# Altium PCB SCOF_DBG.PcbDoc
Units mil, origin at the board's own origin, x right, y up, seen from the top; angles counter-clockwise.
Board outline 1365.03 x 1565.05 mil, 2 copper layers (Top Layer, Bottom Layer); 21 components, 22 nets, 103 pads, 92 vias.
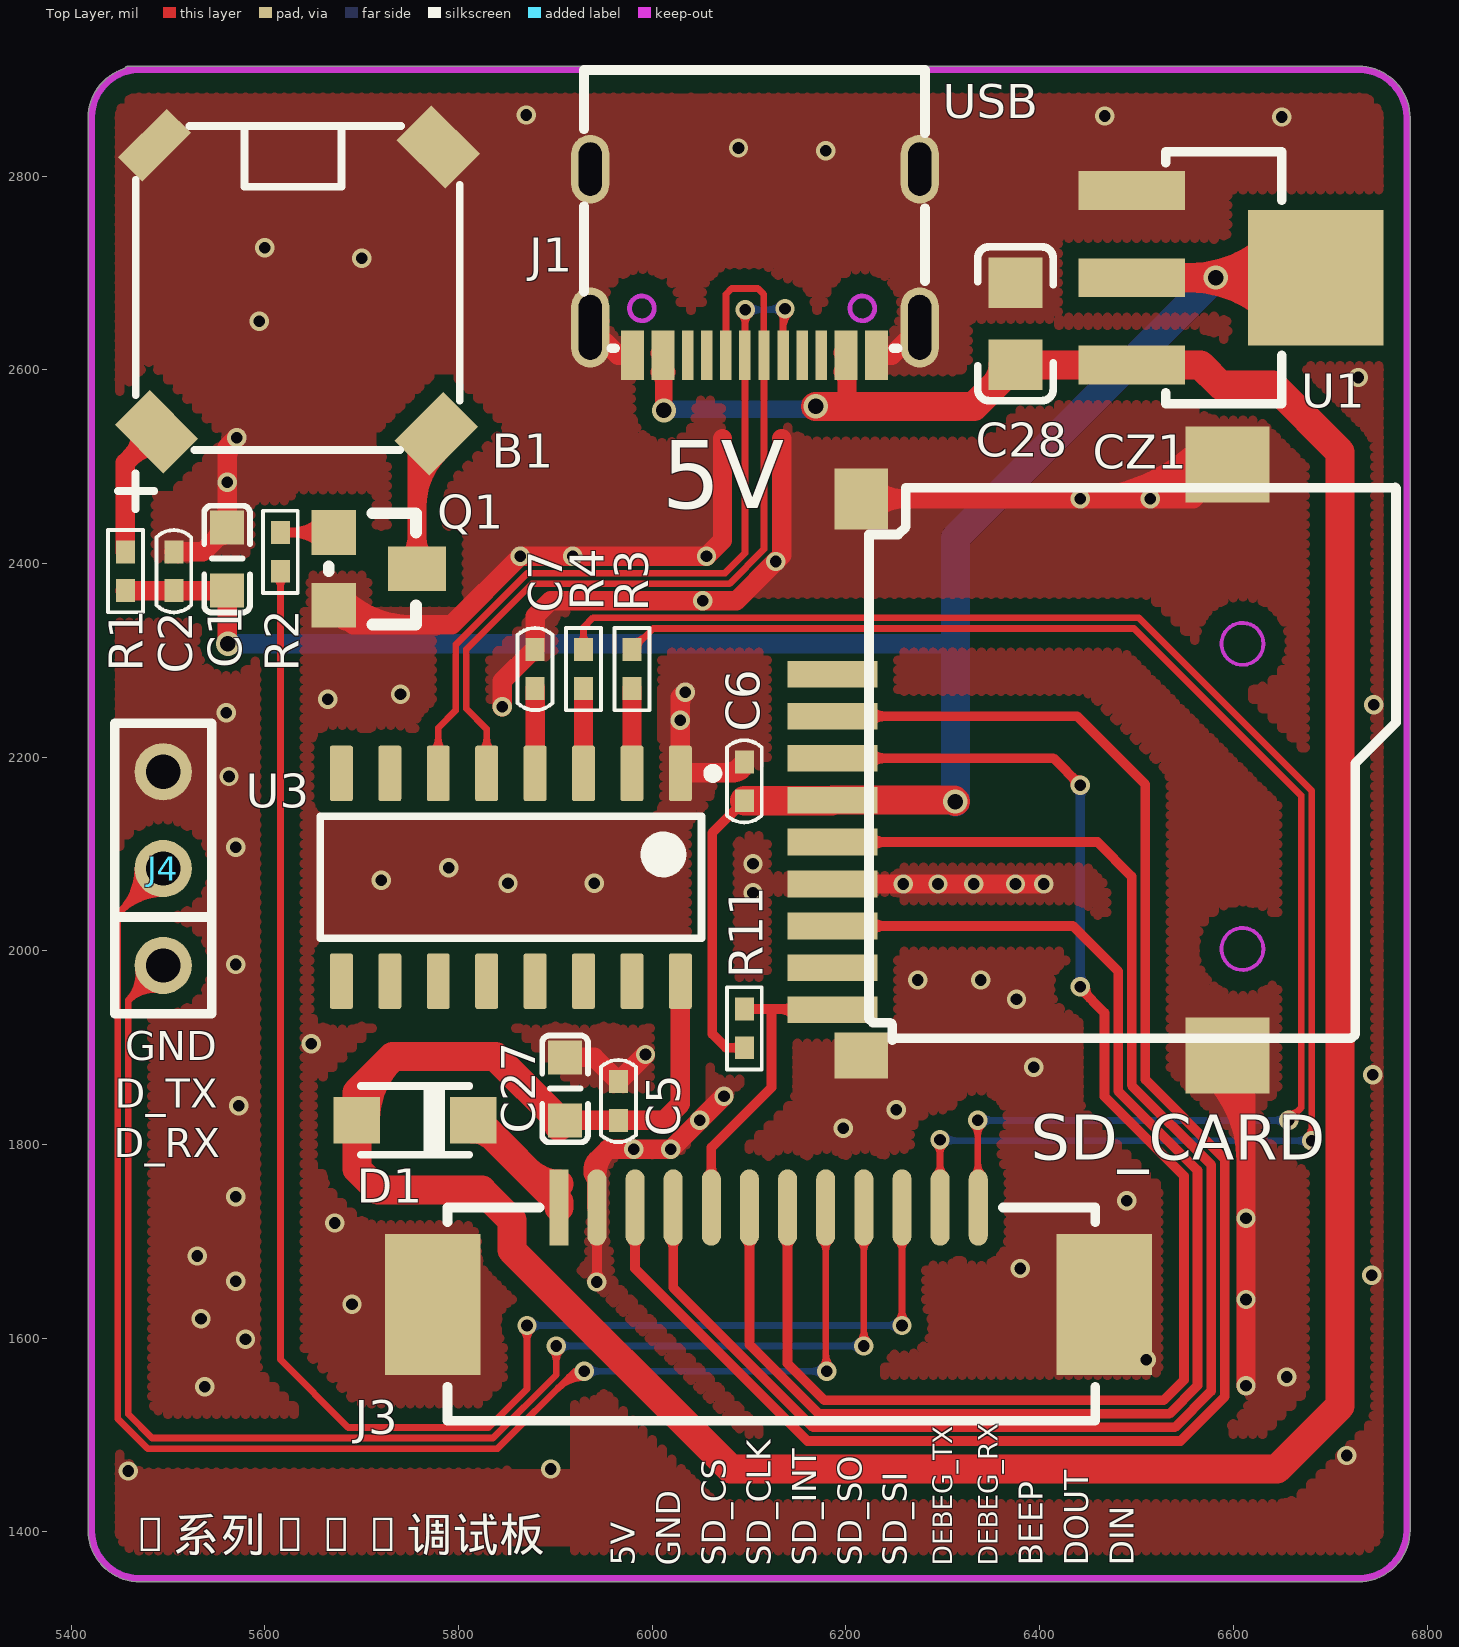
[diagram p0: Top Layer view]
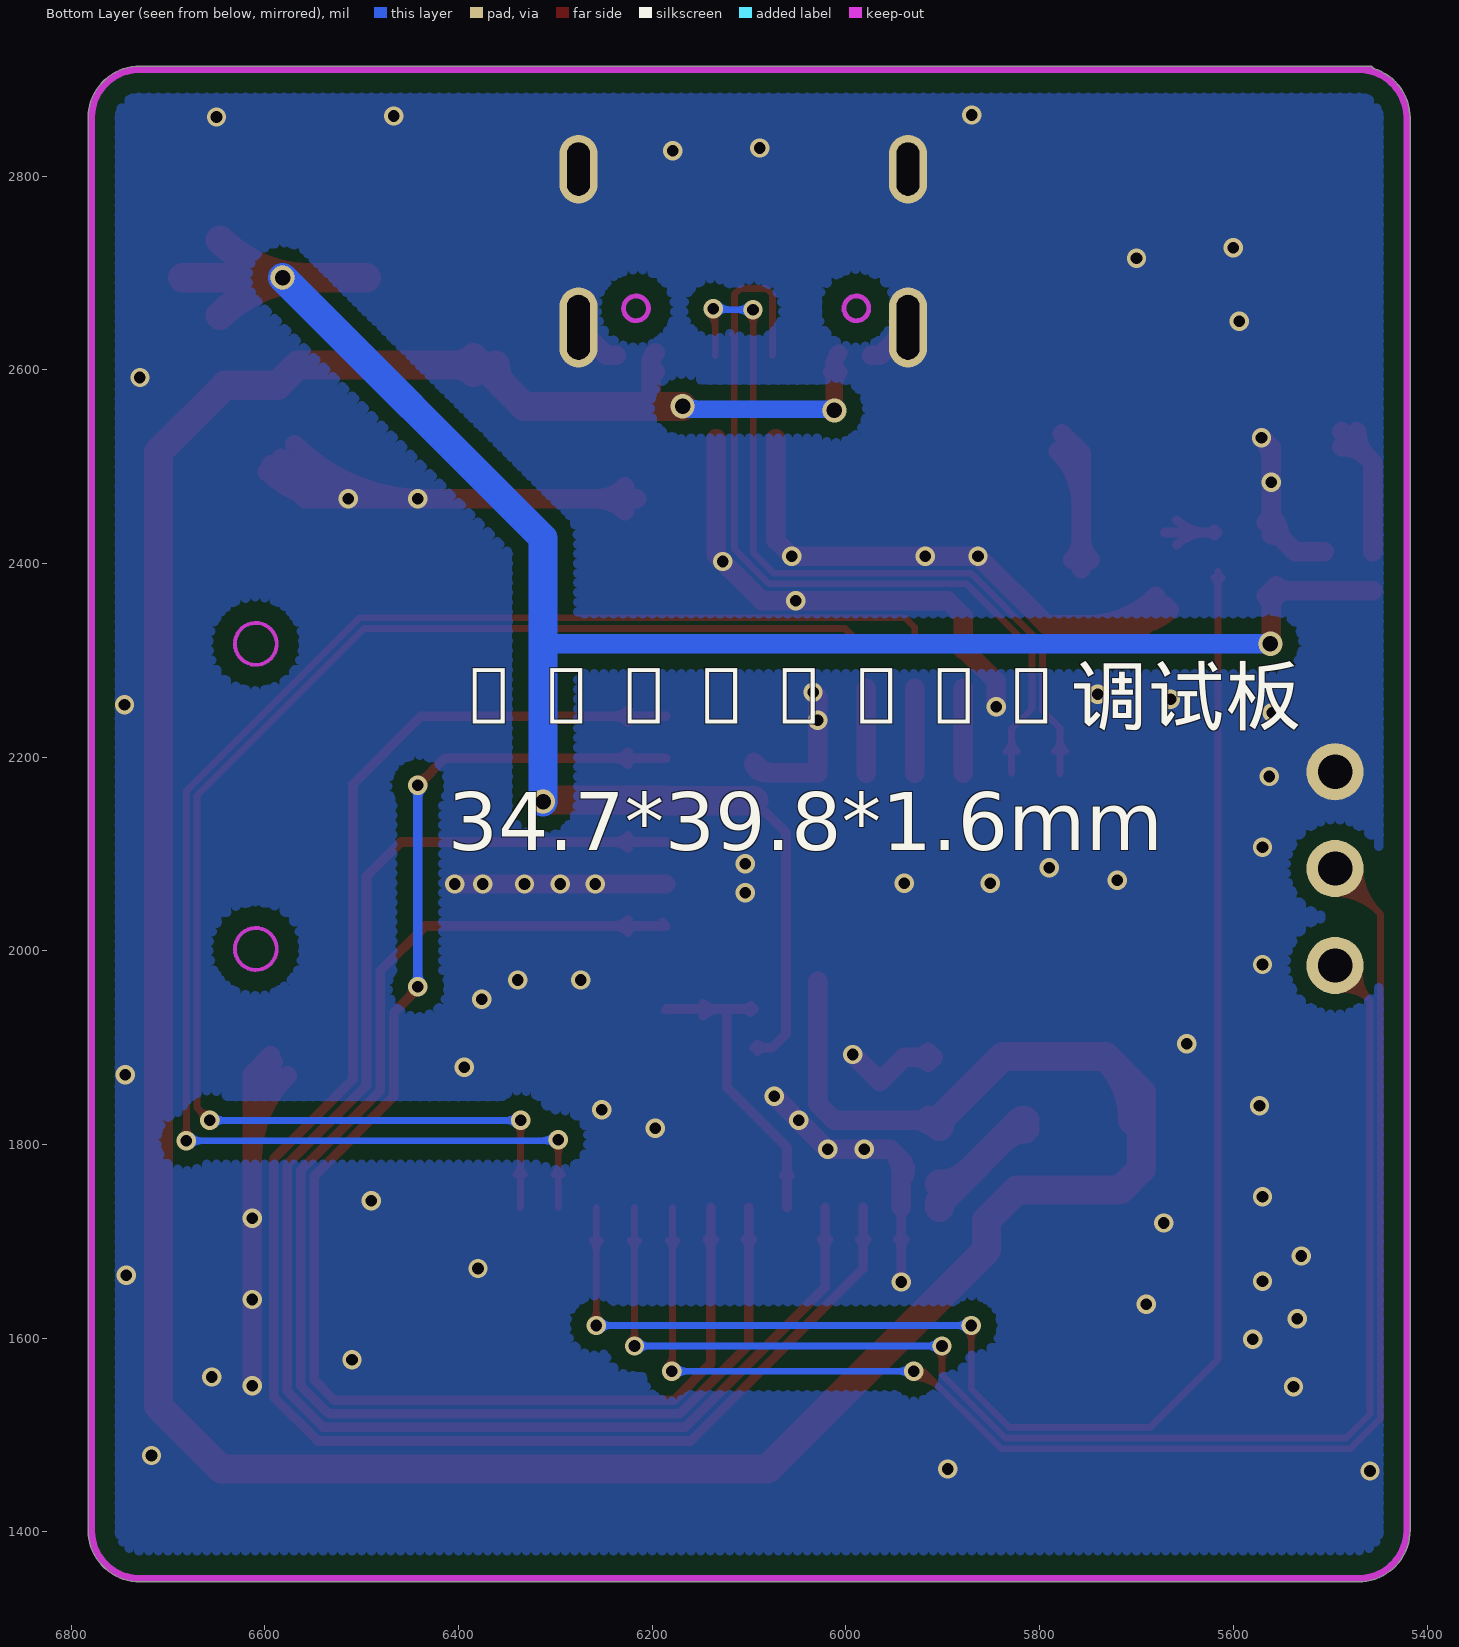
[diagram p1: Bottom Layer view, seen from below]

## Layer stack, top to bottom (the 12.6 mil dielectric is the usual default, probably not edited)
Top Layer: signal copper 1.4
Dielectric: dielectric 12.6, FR-4, Dk 4.8
Bottom Layer: signal copper 1.4

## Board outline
5417.48,1402 5417.48,2860.02 cw(c5471,2860.02) 5455.73,2911.31 cw(c5459,2910.02) 5459,2913.53 6729,2913.53 cw(c6729,2860.02) 6782.52,2860.02 6782.52,1402 cw(c6729,1402) 6729,1348.48 5471,1348.48 cw(c5471,1402)

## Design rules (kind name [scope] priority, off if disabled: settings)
Clearance Clearance_2 [OnLayer('Keep-Out Layer')] p1: gap=20
Clearance Clearance_1 [INPOLY] p2: gap=16
Clearance [All] p3: gap=4
ComponentClearance [All] p1 off: gap=10 collisioncheckmode=3 verticalgap=10 showdistances=FALSE
DiffPairsRouting [All] p1: maxlimit=10 minlimit=6 mostfreqgap=6 maxuncoupledlength=500
FanoutControl Fanout_Default [All] p1: bgadir=Out bgaviamode=Centered fanoutstyle=Auto fanoutdirection=Alternating viagrid=1 // Fanout_Default (Default Rule)
FanoutControl Fanout_Small [(CompPinCount < 5)] p2: bgadir=Out bgaviamode=Centered fanoutstyle=Auto fanoutdirection=OutThenIn viagrid=1 // Fanout_Small (Default Rule)
FanoutControl Fanout_LCC [IsLCC] p4: bgadir=Out bgaviamode=Centered fanoutstyle=Auto fanoutdirection=Alternating viagrid=1 // Fanout_LCC (Default Rule)
FanoutControl Fanout_BGA [IsBGA] p5: bgadir=Out bgaviamode=Centered fanoutstyle=Auto fanoutdirection=Alternating viagrid=1 // Fanout_BGA (Default Rule)
HoleSize [All] p1: absolutevalues=TRUE maxlimit=500 minlimit=1 maxpercent=80.000 minpercent=20.000
HoleToHoleClearance [All] p1 off: gap=10 allowstackedmicrovias=TRUE
MinimumSolderMaskSliver [All] p1 off: minsoldermaskwidth=10
NetAntennae [All] p1 off: netantennaetolerance=0
PasteMaskExpansion [All] p1 off: expansion=0
PolygonConnect [All] p1: connectstyle=Direct reliefconductorwidth=20 reliefentries=4 polygonreliefangle="90 Angle"
PolygonConnect PolygonConnect_1 [ISVIA] p2: connectstyle=Direct reliefconductorwidth=10 reliefentries=4 polygonreliefangle="90 Angle"
PolygonConnect PolygonConnect_3 [(InComponentClass('New Class'))] p3: connectstyle=Relief reliefconductorwidth=10 reliefentries=4 polygonreliefangle="90 Angle"
RoutingVias [All] p1: holewidth=12 width=25 viastyle="Through Hole" minholewidth=12 minwidth=20 maxholewidth=28 maxwidth=50
SilkToSilkClearance [All] p1 off: silktosilkclearance=10
SilkscreenOverComponentPads [IsPad] p1 off: minsilkscreentomaskgap=10
SolderMaskExpansion [All] p1 off: expansion=4
Width [All] p1: maxlimit=500 minlimit=6 preferedwidth=6
15 further rules are at their usual default settings.

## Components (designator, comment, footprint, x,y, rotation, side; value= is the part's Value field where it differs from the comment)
B1 "MLT-8530" BUZZER-SMD 5634,2683 r0 top
C1 "C0603_10uF_6.3V" 0603C 5561,2372 r90 top
C2 "C0402_100nF_16V" 0402C 5506,2412 r270 top
C5 "C0402_100nF_16V" 0402C 5965,1825 r90 top
C6 "C0402_100nF_16V" 0402C 6095,2155 r90 top
C7 "C0402_100nF_16V" 0402C 5879,2271 r90 top
C27 "C0603_100nF_50V" 0603C 5910,1825 r90 top
C28 "C0805_10uF_25V" 0805C 6375,2605 r90 top
CZ1 "TF-15X15" T-F 6185,2285 r0 top
D1 "DSK36" SOD-123F 5755,1825 r0 top
J1 "TYPE-C_COF" TYPE-C_COF 6147.09,2741.97 r180 top locked
J3 "FPC_1.0_12P_翻盖下接" FFC-12S-1.0 6120,1685 r0 top locked
J4 "排针立插2.54_3P*1_H9.5" SIP2.54-3 5495,1985 r90 top
Q1 "MMBT3904_NPN" SOT-23 5671,2432 r270 top
R1 "R0402_7.5Ω" 0402R 5456,2372 r90 top
R2 "R0402_330Ω" 0402R 5616,2392 r90 top
R3 "R0402_22Ω_±1%" 0402R 5979,2311 r270 top
R4 "R0402_22Ω_±1%" 0402R 5929,2311 r270 top
R11 "R0402_10KΩ_±1%" 0402R 6095,1900 r90 top
U1 "AIP1117-3-3GH.TR" SOT-223 6495,2785 r270 top
U3 "IC_CH340C" SOIC-16 5854,2076 r270 top

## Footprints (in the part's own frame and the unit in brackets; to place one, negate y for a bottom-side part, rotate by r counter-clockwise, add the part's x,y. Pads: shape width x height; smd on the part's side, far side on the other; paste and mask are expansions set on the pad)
0402C [mm]
  rect 0.6x0.5 smd: 1(0,0) 2(1.016,0)
  silkscreen extent -0.57,-0.46 1.59,0.46
0402R [mm]
  rect 0.6x0.5 smd: 1(0,0) 2(1.016,0)
  silkscreen extent -0.57,-0.46 1.59,0.46
0603C [mil]
  rect 35x35 smd: 1(0,0) 2(65,0)
  silkscreen extent -23,-24 88,24
0805C [mil]
  rect 52x56 smd: 1(0,0) 2(85,0)
  silkscreen extent -37,-39 122,39, body extent -1,-24 78,23, height 37
BUZZER-SMD [mil]
  rect 50.87x70.87 smd rot 45: 1(-146,-147) 3(145,147)
  rect 50.87x70.87 smd rot 135: 2(143,-149)
  rect 35.43x70.87 smd rot 135: 4(-148,149)
  silkscreen extent -186,-227 167,169
FFC-12S-1.0 [mm]
  rect 0.5x2 smd: 1(-5.5,1.27)
  oval 0.5x2 smd: 2(-4.5,1.27) 3(-3.5,1.27) 4(-2.5,1.27) 5(-1.5,1.27) 6(-0.5,1.27) 7(0.5,1.27) 8(1.5,1.27) 9(2.5,1.27) 10(3.5,1.27) 11(4.5,1.27) 12(5.5,1.27)
  rect 2.5x3.7 smd: 13(-8.802,-1.27) 14(8.802,-1.27)
  silkscreen extent -8.42,-4.32 8.56,1.27
SIP2.54-3 [mm]
  round 1.5 hole 0.9: 1(0,0) 2(2.54,0) 3(5.08,0)
  silkscreen extent -1.27,-1.27 6.35,1.27
SOD-123F [mm]
  rect 1.22x1.22 smd: 1(-1.524,0) 2(1.524,0)
  silkscreen extent -1.42,-0.9 1.43,0.9
SOIC-16 [mm] "SOIC, 16-Leads, Body 10x4mm, Pitch 1.27mm"
  rrect17% 1.45x0.6 smd: 1(-2.725,4.445) 2(-2.725,3.175) 3(-2.725,1.905) 4(-2.725,0.635) 5(-2.725,-0.635) 6(-2.725,-1.905) 7(-2.725,-3.175) 8(-2.725,-4.445) 9(2.725,-4.445) 10(2.725,-3.175) 11(2.725,-1.905) 12(2.725,-0.635) 13(2.725,0.635) 14(2.725,1.905) 15(2.725,3.175) 16(2.725,4.445)
  silkscreen extent -2.85,-5 1.6,5.42, body extent -3,-4.95 3,4.95, height 1.59
SOT-23 [mil]
  rect 46x46 smd: 1(0,0) 2(75,0)
  rect 46x60 smd: 3(37.5,86)
  silkscreen extent -20,-5 95,85
SOT-223 [mil]
  rect 40x110 smd: 1(0,0) 2(90,0) 3(180,0)
  rect 140x140 smd: 4(90,190)
  silkscreen extent -40,35 220,155
T-F [mm]
  rect 1.4x1.2 smd: 0(0.784,-9.985)
  rect 1.4x1.6 smd: 0(0.784,4.615)
  rect 2.2x2 smd: 0(10.384,-9.985) 0(10.384,5.515)
  rect 2.362x0.7 smd: 1(0.03,0.015) 2(0.03,-1.085) 3(0.03,-2.185) 4(0.03,-3.285) 5(0.03,-4.385) 6(0.03,-5.485) 7(0.03,-6.585) 8(0.03,-7.685) 9(0.03,-8.785)
  Keep-Out Layer circle w0.1: c10.778,0.813 r0.55
  Keep-Out Layer circle w0.1: c10.778,-7.188 r0.55
  silkscreen extent 0.99,-9.58 14.8,4.91, body extent 0,-9.29 15.2,4.81, height 1
TYPE-C_COF [mm]
  oval 1x2.1 hole 0.6 slot 1.7 at 90 deg mask+0.05: 1(-3.279,2.495) 2(5.361,2.495)
  oval 1x1.8 hole 0.6 slot 1.4 at 90 deg mask+0.05: 3(-3.279,-1.655) 4(5.361,-1.655)
  rect 0.3x1.3 smd: A1(-2.294,3.23) A4(-1.494,3.23) A5(-0.194,3.23) A6(0.806,3.23) A7(1.306,3.23) A8(2.306,3.23) A9(3.606,3.23) A12(4.406,3.23) B1(4.106,3.23) B4(3.306,3.23) B5(2.806,3.23) B6(1.806,3.23) B7(0.306,3.23) B8(-0.694,3.23) B9(-1.194,3.23) B12(-1.994,3.23)
  Keep-Out Layer circle w0.127: c-1.772,1.995 r0.325
  Keep-Out Layer circle w0.127: c4.008,1.995 r0.325
  silkscreen extent -3.41,-4.26 5.53,3.04

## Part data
B1: library part BUZZER_MLT-8530, "1.09.02.0001"
C1: "1.02.02.0030"
C2: "1.02.01.0026"
C5 C6 C7: "1.19.01.0004"
C27: "1.02.01.0009"
C28: "1.02.02.0009"
CZ1: "1.07.01.0027"
D1: library part D_DSK36, "1.05.02.0014"
J1: "99"
J4: "1.08.03.0012"
Q1: library part Q_MMBT3904_NPN, "1.05.04.0004"
R1: "1.01.01.0011"
R2: "1.01.01.0022"
R3 R4: "1.01.05.0002"
R11: "1.01.05.0007"
U1: library part IC_SPX1117M3-L-3-3/TR, "1.07.02.0004"
U3: library part IC_CH340G/340C, "IC_CH340G/340C"

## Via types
v1: diameter 20, hole 12, Top Layer to Bottom Layer, tented both sides, 87 vias
v2: diameter 25, hole 16, Top Layer to Bottom Layer, tented both sides, 5 vias

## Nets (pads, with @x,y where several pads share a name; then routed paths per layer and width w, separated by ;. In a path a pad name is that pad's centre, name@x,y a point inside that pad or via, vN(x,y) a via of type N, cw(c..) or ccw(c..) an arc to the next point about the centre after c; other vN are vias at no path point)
BEEP: J3.10 R2.1 | length 1858.9
  Top Layer w7: R2.1@5611.52,2385.55 cw(c5600.69,2374.72) 5616,2374.72 cw(c5631.31,2374.72) R2.1@5620.48,2385.55 ; R2.1 5616,1578 5686,1508 5831,1508 5870.69,1547.68 v1(5870.69,1613.2) ; v1@5866.09,1608.61 cw(c5854.99,1597.51) 5870.68,1597.51 cw(c5886.38,1597.51) v1@5875.28,1608.61 ; v1@6253.2,1617.8 ccw(c6242.1,1628.9) 6257.8,1628.9 ccw(c6273.49,1628.9) v1@6262.39,1617.8 ; J3.10@6253.31,1700.99 cw(c6242.48,1690.16) 6257.8,1690.16 cw(c6273.11,1690.16) J3.10@6262.28,1700.99 ; J3.10 v1(6257.8,1613.2) v1@6258,1613
  Bottom Layer w7: v1@5869.89,1614 v1(5870.69,1613.2) 6011,1613.2 ; v1@5875.28,1608.61 cw(c5886.38,1597.51) 5886.38,1613.2 cw(c5886.38,1628.9) v1@5875.28,1617.8 ; 5988.8,1613.2 6011,1613.2 ; v1@6253.2,1608.61 ccw(c6242.1,1597.51) 6242.1,1613.2 ccw(c6242.1,1628.9) v1@6253.2,1617.8 ; v1(6257.8,1613.2) 6011,1613.2
D+: J1.A6 J1.B6 U3.5 | length 894.5
  Top Layer w7: U3.5@5823.12,2205.89 ccw(c5808.94,2220.08) 5829,2220.08 ccw(c5849.06,2220.08) U3.5@5834.88,2205.89 ; U3.5 5829,2229 5808,2250 5808,2311.44 5875.56,2379 6079.56,2379 6115.34,2414.78 J1.A6 6115,2615.15 6115,2678.02 6109,2684.02 6082,2684.02 6075.97,2677.98 J1.B6 ; 6115,2641.12 ccw(c6121.96,2641.12) J1.A6@6117.04,2636.2
D-: J1.A7 J1.B7 U3.6 | length 1003.9
  Top Layer w7: U3.6@5773.12,2205.89 ccw(c5758.94,2220.08) 5779,2220.08 ccw(c5799.06,2220.08) U3.6@5784.88,2205.89 ; U3.6 5779,2230 5797,2248 5797,2316 5871,2390 6075,2390 6095.65,2410.65 J1.A7 ; v1@6091.4,2657.42 cw(c6081.14,2647.16) 6095.65,2647.16 ; 6095.65,2561.02 J1.A7 ; 6095.65,2645.49 cw(c6112.53,2645.49) v1@6100.6,2657.42 ; v1(6096,2662.02) 6095.65,2661.67 J1.A7 ; v1@6132.4,2658.42 cw(c6126.08,2652.09) 6135.02,2652.09 ; J1.B7 6135.02,2661.04 v1(6137,2663.02) ; 6135.02,2642.55 cw(c6157.46,2642.55) v1@6141.6,2658.42
  Bottom Layer w7: v1(6096,2662.02) 6136,2662.02 v1(6137,2663.02) ; v1@6100.6,2657.42 cw(c6111.69,2646.32) 6111.69,2662.02 cw(c6111.69,2677.71) v1@6100.6,2666.61 ; 6118.89,2662.02 ccw(c6118.89,2681.12) v1@6132.4,2667.61 ; 6123.72,2662.02 cw(c6123.72,2649.74) v1@6132.4,2658.42
DEBUG_RX: J3.9 J4.1 | length 1710.7
  Top Layer w7: J4.1@5469.3,1980.86 cw(c5433,1975.01) 5459,1949 ; J4.1@5476.21,1981.97 cw(c5449.67,1977.69) 5468.68,1958.68 cw(c5487.69,1939.67) J4.1@5491.97,1966.21 ; J4.1@5490.86,1959.3 ccw(c5485.01,1923) 5459,1949 ; J4.1 5459,1949 ; v1@5896.29,1587.4 cw(c5885.2,1576.31) 5900.89,1576.31 cw(c5916.58,1576.31) v1@5905.49,1587.4 ; v1(5900.89,1592) 5900.89,1562.33 5835.56,1497 5483.56,1497 5459,1521.56 5459,1949 ; v1@6213.83,1596.6 ccw(c6202.73,1607.69) 6218.43,1607.69 ccw(c6234.12,1607.69) v1@6223.02,1596.6 ; J3.9@6213.94,1700.99 cw(c6203.11,1690.16) 6218.43,1690.16 cw(c6233.74,1690.16) J3.9@6222.91,1700.99 ; v1(6218.43,1592) J3.9
  Bottom Layer w7: v1(5900.89,1592) 6039,1592 ; v1@5905.49,1587.4 cw(c5916.58,1576.31) 5916.58,1592 cw(c5916.58,1607.69) v1@5905.49,1596.6 ; 6019,1592 6039,1592 ; v1@6213.83,1587.4 ccw(c6202.73,1576.31) 6202.73,1592 ccw(c6202.73,1607.69) v1@6213.83,1596.6 ; v1(6218.43,1592) 6039,1592
DEBUG_TX: J3.8 J4.2 | length 1850.8
  Top Layer w7: J4.2@5468.97,2085 cw(c5406.14,2085) 5450.57,2040.57 cw(c5495,1996.14) J4.2@5495,2058.97 ; J4.2@5475.97,2085 cw(c5430.04,2085) 5462.52,2052.52 cw(c5495,2020.04) J4.2@5495,2065.97 ; J4.2 5448,2038 5448,1517 5479,1486 5840.11,1486 5920.11,1566 v1(5929.89,1566) ; 5902.1,1547.99 cw(c5929.89,1520.2) v1@5929.89,1559.5 ; 5914.05,1559.94 cw(c5929.89,1544.1) v1@5929.89,1566.5 ; J3.8@6174.57,1700.99 cw(c6163.74,1690.16) 6179.06,1690.16 cw(c6194.37,1690.16) J3.8@6183.54,1700.99 ; v1@6175.4,1570.6 ccw(c6166.59,1579.41) 6179.06,1579.41 ; v1@6179.06,1566.94 J3.8 ; 6179.06,1583.97 ccw(c6197.97,1583.97) v1@6184.6,1570.6
  Bottom Layer w7: v1(5929.89,1566) v1(6180,1566) ; v1@5934.49,1561.4 cw(c5945.58,1550.31) 5945.58,1566 cw(c5945.58,1581.69) v1@5934.49,1570.6 ; v1@6175.4,1561.4 ccw(c6164.31,1550.31) 6164.31,1566 ccw(c6164.31,1581.69) v1@6175.4,1570.6
DIN: J3.12 R3.1 | length 1670.3
  Top Layer w7: R3.1 6001,2333 6497.44,2333 6670,2160.44 6670,1838 v1(6657,1825) ; R3.1@5979,2319.31 ccw(c5979,2339.38) 5993.19,2325.19 ; R3.1@5985.34,2312.97 cw(c5995.9,2312.97) R3.1@5988.44,2320.44 ; v1@6331.4,1820.4 cw(c6320.31,1809.31) 6336,1809.31 cw(c6351.69,1809.31) v1@6340.6,1820.4 ; J3.12@6332.05,1769.01 ccw(c6322.52,1778.55) 6336,1778.55 ; 6336,1781.13 ccw(c6353.14,1781.13) J3.12@6341.02,1769.01 ; v1(6336,1825) 6336,1735.54 J3.12 ; v1@6657,1831.5 ccw(c6657,1847.19) 6668.1,1836.1 ccw(c6679.19,1825) v1@6663.5,1825
  Bottom Layer w7: v1(6336,1825) v1(6657,1825) ; v1@6340.6,1820.4 cw(c6351.69,1809.31) 6351.69,1825 cw(c6351.69,1840.69) v1@6340.6,1829.6 ; v1@6652.4,1820.4 ccw(c6641.31,1809.31) 6641.31,1825 ccw(c6641.31,1840.69) v1@6652.4,1829.6
DOUT: J3.11 R4.1 | length 1819.5
  Top Layer w7: R4.1@5924.52,2317.45 ccw(c5913.69,2328.28) 5929,2328.28 ccw(c5944.31,2328.28) R4.1@5933.48,2317.45 ; R4.1 5929,2334 5939,2344 6502,2344 6681,2165 v1(6681,1804) v1@6681,1800 ; v1@6292.4,1800.4 cw(c6281.31,1789.31) 6297,1789.31 cw(c6312.69,1789.31) v1@6301.6,1800.4 ; J3.11@6292.68,1769.01 ccw(c6282.25,1779.44) 6297,1779.44 ; 6297,1780.24 ccw(c6312.88,1780.24) J3.11@6301.65,1769.01 ; v1(6297,1805) 6297,1735.17 J3.11 ; v1@6676.4,1808.6 ccw(c6665.31,1819.69) 6681,1819.69 ccw(c6696.69,1819.69) v1@6685.6,1808.6
  Bottom Layer w7: v1(6297,1805) 6298,1804 v1(6681,1804) ; v1@6301.6,1800.4 cw(c6310.28,1791.72) 6310.28,1804 ; v1@6301.6,1809.6 ccw(c6315.11,1823.11) 6315.11,1804 ; v1@6676.4,1799.4 ccw(c6665.31,1788.31) 6665.31,1804 ccw(c6665.31,1819.69) v1@6676.4,1808.6
GND: B1.3 B1.4 C1.2 C2.1 C5.2 C6.2 C7.2 C27.2 C28.2 CZ1.0 CZ1.6 J1.1 J1.2 J1.3 J1.4 J1.A1 J1.A12 J1.B1 J1.B12 J3.2 J3.13 J3.14 J4.3 Q1.2 U1.1 U3.1 | length 3765.8
  Top Layer w10: v1@5939.3,1661.7 ccw(c5930.76,1670.24) 5942.83,1670.24 ccw(c5954.91,1670.24) v1@5946.37,1661.7 ; J3.2@5939.41,1702.05 cw(c5931.14,1693.78) 5942.83,1693.78 cw(c5954.53,1693.78) J3.2@5946.26,1702.05 ; J3.2 v1(5942.83,1658.17) v1@5943,1658
  Top Layer w20: C2.1 5536,2412 C1.2 5561,2520 v1(5571,2530) ccw(c5595.14,2505.86) 5561,2505.86 ; C1.2@5553.5,2437 cw(c5535.39,2437) 5548.2,2424.2 cw(c5561,2411.39) C1.2@5561,2429.5 ; C1.2@5555.7,2442.3 ccw(c5542.89,2455.11) 5561,2455.11 ccw(c5579.11,2455.11) C1.2@5566.3,2442.3 ; Q1.2@5666.05,2352.05 ccw(c5702.69,2388.69) 5702.69,2336.87 ; Q1.2 5691.13,2336.87 5793.13,2336.87 v1(5863.75,2407.5) v1(6056,2407.5) 6072.5,2424 6072.5,2529 ; Q1.2@5680.19,2366.19 ccw(c5750.97,2436.97) 5750.97,2336.87 ; v1(5845,2252) 5845,2278.45 5877.55,2311 C7.2 5879,2345.5 5895,2361.5 v1(6052,2361.5) 6086.81,2361.5 v1(6127.34,2402.04) 6133.84,2408.53 6133.84,2529 ; C27.2 5940,1890 C5.2 v1(5993,1893) ; C27.2@5915.3,1884.7 cw(c5928.11,1871.89) 5928.11,1890 cw(c5928.11,1908.11) C27.2@5915.3,1895.3 ; J1.2 5964.94,2614.81 J1.A12 ; J3.2@5942.72,1764.42 cw(c5952.6,1774.07) 5942.83,1783.83 ; J3.2@5942.68,1764.52 cw(c5981.59,1767.41) 5954,1795 ; J3.2 5942.83,1783.83 ; 6029,2254.93 cw(c6046.07,2254.93) v1(6034,2267) 6029,2262 U3.1 6029.72,2184 6084,2184 ; 6073.58,2184 ccw(c6073.58,2214.46) C6.2@6095.11,2192.92 ; v1(6074,1850) v1(6019,1795) 5954,1795 ; C6.2 6084,2184 ; C6.2@6095.15,2193 cw(c6084,2195.41) 6084,2184 ; CZ1.6 CZ1.6 v1(6404,2069) ; CZ1.0@6215.87,2466.68 6558.39,2466.68 CZ1.0@6593.82,2502.12 ; CZ1.0@6228.28,2454.27 cw(c6258.26,2424.29) 6258.26,2466.68 cw(c6258.26,2509.08) CZ1.0@6228.28,2479.1 ; J1.A1 6247.23,2614.81 J1.1 ; v1@6433.43,2466.68 ccw(c6433.43,2658.57) CZ1.0@6569.11,2522.89 ; 6481.72,2466.68 ccw(c6481.72,2610.28) CZ1.0@6583.26,2508.74 ; 6530,2466.68 ccw(c6530,2562) CZ1.0@6597.4,2494.6 ; CZ1.0@6576.99,1871.11 cw(c6490.05,1784.17) 6613,1784.17 ; CZ1.0@6591.13,1885.26 cw(c6538.33,1832.46) 6613,1832.46 ; CZ1.0@6593.82,1891.88 6613,1872.7 v1(6613,1551) ; 5942.83,1783.83 5954,1795
  other v1: 5459,1463 5895,1465 6717,1479 5538,1550 6655,1560 6510,1578 5580,1599 5534,1620 5690,1635 6613,1640 5570,1659 6743,1665 6380,1672 5530,1685 5672,1719 6613,1724 6490,1742 5570,1746 5981,1795 6197,1817 6048.95,1824.95 6252,1836 5573,1840 6744,1872 6394,1880 5648,1904 6376,1950 6274,1970 6339,1970 5570,1986 6104,2060 6259,2069 6295,2069 6332,2069 6375,2069 5851,2070 5940,2070 5720,2073 5790,2086 6104,2090 5570,2107 5563,2180 6029,2238 5560,2246 6745,2254 5665,2260 5740,2265 5918,2407.5 6442,2466.68 6514,2466.68 5561,2484 6729,2592 5594,2650 5700,2715 5600,2726 6179,2826 6089,2829 6650,2861 6467,2862 5870,2863
NetB1_1: B1.1 R1.2 | length 195.8
  Top Layer w20: R1.2 5456,2504 B1.1 ; B1.1@5472.57,2536 cw(c5435.31,2536) 5461.65,2509.65 cw(c5488,2483.31) B1.1@5488,2520.57
NetB1_2: B1.2 Q1.3 | length 261
  Top Layer w20: Q1.3@5747.81,2403.69 ccw(c5725.62,2425.88) 5757,2425.88 ccw(c5788.38,2425.88) Q1.3@5766.19,2403.69 ; Q1.3 5757,2514 B1.2 ; 5757,2458.46 cw(c5838.4,2458.46) B1.2@5780.84,2516.02
NetC7_1: C7.1 U3.4 | length 87.7
  Top Layer w20: U3.4 C7.1
NetD1_2: D1.2 J3.1 | length 189.4
  Top Layer w30: D1.2@5815,1815.98 cw(c5815,1784.56) D1.2@5837.22,1806.78 ; D1.2 5819,1825 5903.46,1740.54 J3.1 ; 5871.31,1772.69 ccw(c5903.46,1804.84) J3.1@5903.46,1759.37
NetQ1_1: Q1.1 R2.2 | length 141.6
  Top Layer w10: R2.2 Q1.1 ; R2.2@5619.42,2428.58 cw(c5627.69,2420.31) 5627.69,2432 cw(c5627.69,2443.69) R2.2@5619.42,2435.42 ; Q1.1@5658.27,2419.27 ccw(c5627.54,2388.54) 5627.54,2432 ccw(c5627.54,2475.46) Q1.1@5658.27,2444.73
RXD: R4.2 U3.3 | length 87.7
  Top Layer w20: U3.3 R4.2
SD_CLK: CZ1.5 J3.4 | length 1653.9
  Top Layer w10: J3.4@6018.15,1702.05 cw(c6009.88,1693.78) 6021.57,1693.78 cw(c6033.27,1693.78) J3.4@6025,1702.05 ; J3.4 6021.57,1652.51 6166.09,1508 6539.6,1508 6577,1545.4 6577,1779.2 6495,1861.2 6495,2077 6459.65,2112.35 CZ1.5 ; CZ1.5@6225.11,2106.15 cw(c6240.09,2091.16) 6240.09,2112.35 cw(c6240.09,2133.55) CZ1.5@6225.11,2118.56
SD_CS: CZ1.2 J3.3 | length 1834.3
  Top Layer w10: J3.3@5978.78,1702.05 cw(c5970.51,1693.78) 5982.2,1693.78 cw(c5993.9,1693.78) J3.3@5985.63,1702.05 ; J3.3 5982.2,1672.08 6160.29,1494 6545.4,1494 6591,1539.6 6591,1785 6509,1867 6509,2172 6438.72,2242.28 CZ1.2 ; CZ1.2@6225.11,2236.07 cw(c6240.09,2221.08) 6240.09,2242.28 cw(c6240.09,2263.47) CZ1.2@6225.11,2248.48
SD_INT: CZ1.9 J3.5 R11.2 | length 392.3
  Top Layer w10: J3.5@6057.52,1767.95 ccw(c6049.25,1776.22) 6060.94,1776.22 ccw(c6072.64,1776.22) J3.5@6064.37,1767.95 ; J3.5 6060.94,1796.94 6123,1859 6123,1940 ; R11.2 6123,1940 ; R11.2@6098.42,1936.58 cw(c6106.69,1928.31) 6106.69,1940 cw(c6106.69,1951.69) R11.2@6098.42,1943.42 ; 6130.16,1940 cw(c6130.16,1915.82) CZ1.9@6147.26,1932.92 ; 6134.38,1940 ccw(c6134.38,1958.21) CZ1.9@6147.26,1945.33 ; CZ1.9 6185.31,1940 6123,1940
SD_SI: CZ1.3 J3.7 | length 1643.7
  Top Layer w10: J3.7@6136.26,1702.05 cw(c6127.99,1693.78) 6139.69,1693.78 cw(c6151.38,1693.78) J3.7@6143.11,1702.05 ; J3.7 6139.69,1574 6177.69,1536 6528,1536 6549,1557 6549,1767.6 6467,1849.6 6467,1936 6442,1961 v1(6442,1963) ; CZ1.3 6414.03,2198.97 v1(6442,2171) ; CZ1.3@6225.11,2192.76 cw(c6240.09,2177.77) 6240.09,2198.97 cw(c6240.09,2220.16) CZ1.3@6225.11,2205.18 ; v1@6437,2171 ccw(c6424.93,2171) 6433.46,2179.54 ccw(c6442,2188.07) v1@6442,2176 ; v1@6447,1963 ccw(c6463.9,1963) 6451.95,1951.05
  Bottom Layer w10: v1@6438.46,1966.54 ccw(c6429.93,1975.07) 6442,1975.07 ccw(c6454.07,1975.07) v1@6445.54,1966.54 ; v1@6438.46,2167.46 cw(c6429.93,2158.93) 6442,2158.93 cw(c6454.07,2158.93) v1@6445.54,2167.46 ; v1(6442,1963) v1(6442,2171) v1@6443,2172
SD_SO: CZ1.7 J3.6 | length 1478.1
  Top Layer w10: J3.6@6096.89,1702.05 cw(c6088.62,1693.78) 6100.32,1693.78 cw(c6112.01,1693.78) J3.6@6103.74,1702.05 ; J3.6 6100.31,1593.57 6171.89,1522 6533.8,1522 6563,1551.2 6563,1773.4 6481,1855.4 6481,1979 6434.26,2025.74 CZ1.7 CZ1.7@6189.44,2029 ; CZ1.7@6225.11,2019.53 cw(c6240.09,2004.54) 6240.09,2025.74 cw(c6240.09,2046.94) CZ1.7@6225.11,2031.95
TXD: R3.2 U3.2 | length 87.7
  Top Layer w20: U3.2 R3.2
VCC5V: C5.1 C27.1 C28.1 D1.1 J1.A4 J1.A9 J1.B4 J1.B9 U1.3 U3.16 | length 3867.3
  Top Layer w12: v2(6168.79,2562.23) v2@6169,2562.02
  Top Layer w18: J1.A9@6007.29,2597.31 cw(c5995.92,2585.94) 6012,2585.94 ; J1.A9@6007.29,2617 cw(c5995.92,2605.63) J1.B4@6012,2605.63 ; v2(6012,2558.02) J1.B4@6012,2607.91 ; J1.B4@6012,2590.73 cw(c6021.31,2590.73) J1.B4@6014.73,2597.31
  Top Layer w20: C27.1 C5.1 6012,1825 6029,1842 U3.16 ; C27.1@5915.3,1819.7 cw(c5928.11,1806.89) 5928.11,1825 cw(c5928.11,1843.11) C27.1@5915.3,1830.3 ; J1.B9@6196.97,2598.02 cw(c6187.25,2588.3) 6201,2588.3 ; J1.B9@6196.97,2617.71 cw(c6187.25,2607.99) J1.A4@6201,2607.99 ; J1.A4@6201,2610.14 6201,2568.23 6207,2562.23
  Top Layer w25: C28.1@6372,2602 C28.1 C28.1@6375,2602
  Top Layer w30: D1.1@5704.02,1825 cw(c5795.79,1825) 5730.9,1889.9 ; C27.1@5903.46,1818.46 C27.1 5904,1825 5838,1891 5732,1891 5695,1854 D1.1 5695,1775 5717,1753 5824,1753 5855,1722 5855,1691 6081,1465 6645,1465 6710,1530 6710,2515 6641,2584 6587,2584 6566,2605 U1.3 C28.1 ; v2(6168.79,2562.23) 6207,2562.23 6332.23,2562.23 C28.1@6372,2602 ; C28.1@6352.81,2582.81 ccw(c6330.62,2605) C28.1@6362,2605 ; C28.1@6384.78,2597.22 cw(c6403.56,2578.44) 6403.56,2605 cw(c6403.56,2631.56) C28.1@6384.78,2612.78
  Bottom Layer w12: v2@6167.57,2561.02 v2@6169,2561.02
  Bottom Layer w18: v2(6012,2558.02) 6013.34,2559.36 6165.92,2559.36 6167.57,2561.02 v2(6168.79,2562.23) ; 6153.41,2559.36 ccw(c6153.41,2577.61) v2@6166.31,2564.7
VDD3V3: C1.1 C2.2 C6.1 CZ1.4 R1.1 R11.1 U1.2 U1.4 | length 2564
  Top Layer w10: 6083.37,2143.37 cw(c6095,2131.75) C6.1@6095,2148.19 ; R11.1@6091.58,1896.58 ccw(c6083.31,1888.31) 6083.31,1900 ccw(c6083.31,1911.69) R11.1@6091.58,1903.42 ; R11.1 6076,1900 6062,1914 6062,2122 C6.1
  Top Layer w20: R1.1 C2.2 C1.1 5561,2318 v2(5561.79,2317.21) v2@5562,2317 ; C1.1@5555.7,2377.3 cw(c5542.89,2390.11) 5542.89,2372 cw(c5542.89,2353.89) 5555.7,2366.7 cw(c5542.89,2353.89) 5561,2353.89 cw(c5579.11,2353.89) C1.1@5566.3,2366.7
  Top Layer w30: C6.1 6185.52,2155 CZ1.4 6311.34,2155.66 v2(6312.79,2154.21) ; U1.2 U1.4 ; U1.4@6646.11,2656.11 ccw(c6552.22,2562.22) 6552.22,2695 ccw(c6552.22,2827.78) U1.4@6646.11,2733.89
  Bottom Layer w20: v2(5561.79,2317.21) 6310.79,2317.21 6313,2315
  Bottom Layer w30: v2@6313,2154 6313,2315 6313,2426.43 v2(6581.79,2695.21)
pads on no net: CZ1.1 CZ1.8 J1.A5 J1.A8 J1.B5 J1.B8 U3.7 U3.8 U3.9 U3.10 U3.11 U3.12 U3.13 U3.14 U3.15

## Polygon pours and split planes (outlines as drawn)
GND on Top Layer "Bottom Layer-No Net" (hatched 90Degree grid 10 track 10, remove dead copper, pour order 1001): 5417,1379 5417,2910.02 5476,2910.02 6783,2910.02 6783,1378
GND on Bottom Layer "Bottom Layer-No Net" (hatched 90Degree grid 10 track 10, remove dead copper, pour order 1000): 5417,1379 5417,2910.02 5476,2910.02 6783,2910.02 6783,1378

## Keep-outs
Keep-Out Layer:
  lines w7: 5459,2910.02 6729,2910.02 cw(c6729,2860.02) 6779,2860.02 6779,2565 6779,1402 cw(c6729,1402) 6729,1352 5471,1352 cw(c5471,1402) 5421,1402 5421,1822 5421,2860.02 cw(c5471,2860.02) 5471,2910.02 5472,2910.02

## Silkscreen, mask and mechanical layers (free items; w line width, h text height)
Top Overlay:
  text "USB" at 6300,2848 h60
  text "5V" at 6010,2434 h120
  text "GND" at 5456,1887 h30
  text "D_TX" at 5445,1838 h30
  text "D_RX" at 5444,1787 h30
  text "S系列COF调试板" at 5458,1368 h60
  text "5V" at 5982,1365 h25 r90
  text "GND" at 6028.82,1365 h25 r90
  text "SD_CS" at 6075.64,1365 h25 r90
  text "SD_CLK" at 6122.45,1365 h25 r90
  text "SD_INT" at 6169.27,1365 h25 r90
  text "SD_SO" at 6216.09,1365 h25 r90
  text "SD_SI" at 6262.91,1365 h25 r90
  text "DEBEG_TX" at 6309.73,1365 h20 r90
  text "DEBEG_RX" at 6356.54,1365 h20 r90
  text "BEEP" at 6403.36,1365 h25 r90
  text "DOUT" at 6450.18,1365 h25 r90
  text "DIN" at 6497,1365 h25 r90
Bottom Overlay:
  text "S043_COF调试板" at 6408.42,2215.54 h100
  text "34.7*39.8*1.6mm" at 6411,2104 h60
